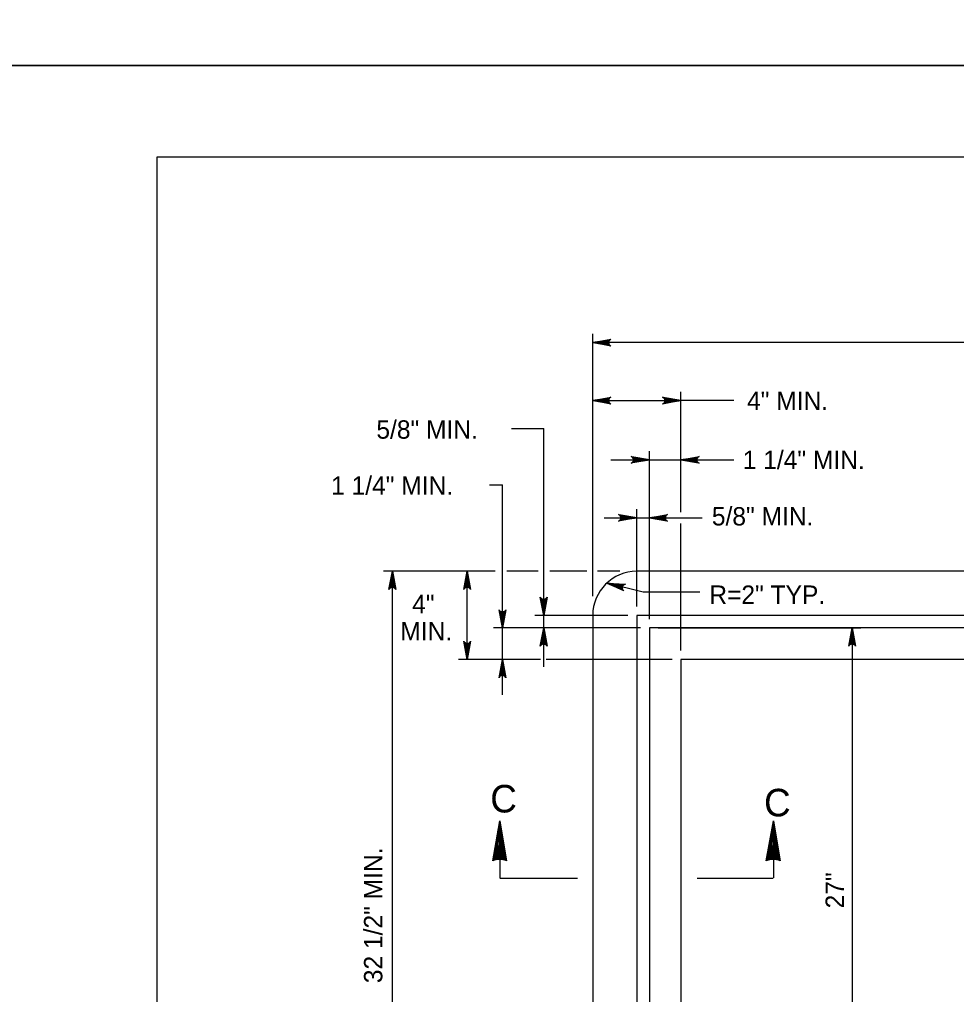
# Model space of a CAD drawing. Extents: x 2087776 to 2104538, y 970919 to 982612.
# Drawn here: x 2096108 to 2096610, y 976268 to 976790 of the extents above; entities that cross this region are included whole.
import ezdxf

# ---------------------------------------------------------------- set-up
doc = ezdxf.new("R2010")
doc.units = 0
doc.layers.add('1', color=7, linetype='Continuous')
doc.layers.add('PLT-BNDY', color=7, linetype='Continuous')

msp = doc.modelspace()

# ---------------------------------------------------------------- linework, layer by layer
at = {"layer": '1'}
for p, q in [((2096414.81, 976481.38), (2096414.81, 976622.01)), ((2096741.69, 976617.29), (2096414.81, 976617.29)), ((2096462.05, 976530.67), (2096462.05, 976590.95)), ((2096414.81, 976586.22), (2096462.05, 976586.22)), ((2096490.4, 976586.22), (2096462.05, 976586.22)), ((2096445.18, 976469.12), (2096445.18, 976559.18)), ((2096462.05, 976526.42), (2096462.05, 976559.18)), ((2096424.44, 976554.45), (2096490.4, 976554.45)), ((2096438.43, 976475.88), (2096438.43, 976528.11)), ((2096445.18, 976469.12), (2096445.18, 976528.11)), ((2096420.99, 976523.39), (2096473.52, 976523.39)), ((2096462.05, 976452.25), (2096462.05, 976520.3)), ((2096462.05, 976452.25), (2096462.05, 976515.36)), ((2096362.61, 976494.77), (2096302.73, 976494.77)), ((2096307.45, 976130.34), (2096307.45, 976494.77)), ((2096347.55, 976447.53), (2096347.55, 976494.77)), ((2096385.53, 976494.77), (2096368.86, 976494.77)), ((2096411.58, 976494.77), (2096391.78, 976494.77)), ((2096429.3, 976494.77), (2096417.31, 976494.77)), ((2096433.71, 976471.15), (2096383.84, 976471.15)), ((2096440.45, 976464.4), (2096361.72, 976464.4)), ((2096440.45, 976464.4), (2096383.84, 976464.4)), ((2096449.9, 976464.4), (2096558.58, 976464.4)), ((2096553.85, 976464.4), (2096553.85, 976160.71)), ((2096386.75, 976447.53), (2096342.82, 976447.53)), ((2096384.12, 976447.53), (2096361.72, 976447.53)), ((2096457.33, 976447.53), (2096389.92, 976447.53)), ((2096457.33, 976447.53), (2096391.61, 976447.53)), ((2096365, 976340.37), (2096365, 976330.5)), ((2096511.64, 976340.37), (2096511.64, 976330.5)), ((2096364.96, 976330.42), (2096406.6, 976330.42)), ((2096470.79, 976330.42), (2096511.6, 976330.42))]:
    msp.add_line(p, q, dxfattribs=at)
for points in [[(2098759.93, 974866.19), (2098759.93, 976716.58), (2096181.19, 976716.58), (2096181.19, 974866.19), (2098759.93, 974866.19), (2098759.93, 974952.67), (2098103.76, 974952.67), (2098103.76, 975164.86), (2098759.93, 975164.86), (2098759.93, 975259.89), (2098103.76, 975259.89), (2098103.76, 974866.19), (2098362.29, 974866.19), (2098362.29, 974952.67), (2098362.29, 974866.19), (2098614.92, 974866.19), (2098614.92, 974952.67), (2098614.92, 974912.26), (2098759.93, 974912.26)], [(2096414.81, 976617.29), (2096424.59, 976619.12), (2096424.22, 976618.86), (2096423.84, 976618.6), (2096423.65, 976618.27), (2096423.45, 976617.94), (2096423.4, 976617.61), (2096423.34, 976617.29), (2096423.4, 976616.96), (2096423.45, 976616.63), (2096423.65, 976616.3), (2096423.84, 976615.97), (2096424.22, 976615.71), (2096424.59, 976615.45), (2096414.81, 976617.29), (2096424.22, 976615.71), (2096423.84, 976615.97), (2096414.81, 976617.29), (2096423.65, 976616.3), (2096423.45, 976616.63), (2096414.81, 976617.29), (2096423.4, 976616.96), (2096423.34, 976617.29), (2096414.81, 976617.29), (2096423.4, 976617.61), (2096423.45, 976617.94), (2096414.81, 976617.29), (2096423.65, 976618.27), (2096423.84, 976618.6), (2096414.81, 976617.29), (2096424.22, 976618.86)], [(2096414.81, 976586.22), (2096424.59, 976588.06), (2096424.22, 976587.8), (2096423.84, 976587.54), (2096423.65, 976587.21), (2096423.45, 976586.88), (2096423.4, 976586.55), (2096423.34, 976586.22), (2096423.4, 976585.9), (2096423.45, 976585.57), (2096423.65, 976585.24), (2096423.84, 976584.91), (2096424.22, 976584.65), (2096424.59, 976584.39), (2096414.81, 976586.22), (2096424.22, 976584.65), (2096423.84, 976584.91), (2096414.81, 976586.22), (2096423.65, 976585.24), (2096423.45, 976585.57), (2096414.81, 976586.22), (2096423.4, 976585.9), (2096423.34, 976586.22), (2096414.81, 976586.22), (2096423.4, 976586.55), (2096423.45, 976586.88), (2096414.81, 976586.22), (2096423.65, 976587.21), (2096423.84, 976587.54), (2096414.81, 976586.22), (2096424.22, 976587.8)], [(2096462.05, 976586.22), (2096452.27, 976584.39), (2096452.64, 976584.65), (2096453.02, 976584.91), (2096453.22, 976585.24), (2096453.41, 976585.57), (2096453.47, 976585.9), (2096453.52, 976586.22), (2096453.47, 976586.55), (2096453.41, 976586.88), (2096453.22, 976587.21), (2096453.02, 976587.54), (2096452.64, 976587.8), (2096452.27, 976588.06), (2096462.05, 976586.22), (2096452.64, 976587.8), (2096453.02, 976587.54), (2096462.05, 976586.22), (2096453.22, 976587.21), (2096453.41, 976586.88), (2096462.05, 976586.22), (2096453.47, 976586.55), (2096453.52, 976586.22), (2096462.05, 976586.22), (2096453.47, 976585.9), (2096453.41, 976585.57), (2096462.05, 976586.22), (2096453.22, 976585.24), (2096453.02, 976584.91), (2096462.05, 976586.22), (2096452.64, 976584.65)], [(2096371.33, 976571.27), (2096388.56, 976571.27)], [(2096388.56, 976443.6), (2096388.56, 976571.27)], [(2096445.18, 976554.45), (2096435.39, 976552.62), (2096435.77, 976552.88), (2096436.14, 976553.14), (2096436.34, 976553.47), (2096436.53, 976553.8), (2096436.59, 976554.12), (2096436.65, 976554.45), (2096436.59, 976554.78), (2096436.53, 976555.11), (2096436.34, 976555.44), (2096436.14, 976555.76), (2096435.77, 976556.03), (2096435.39, 976556.29), (2096445.18, 976554.45), (2096435.77, 976556.03), (2096436.14, 976555.76), (2096445.18, 976554.45), (2096436.34, 976555.44), (2096436.53, 976555.11), (2096445.18, 976554.45), (2096436.59, 976554.78), (2096436.65, 976554.45), (2096445.18, 976554.45), (2096436.59, 976554.12), (2096436.53, 976553.8), (2096445.18, 976554.45), (2096436.34, 976553.47), (2096436.14, 976553.14), (2096445.18, 976554.45), (2096435.77, 976552.88)], [(2096462.05, 976554.45), (2096471.84, 976556.29), (2096471.46, 976556.03), (2096471.08, 976555.76), (2096470.89, 976555.44), (2096470.7, 976555.11), (2096470.64, 976554.78), (2096470.58, 976554.45), (2096470.64, 976554.12), (2096470.7, 976553.8), (2096470.89, 976553.47), (2096471.08, 976553.14), (2096471.46, 976552.88), (2096471.84, 976552.62), (2096462.05, 976554.45), (2096471.46, 976552.88), (2096471.08, 976553.14), (2096462.05, 976554.45), (2096470.89, 976553.47), (2096470.7, 976553.8), (2096462.05, 976554.45), (2096470.64, 976554.12), (2096470.58, 976554.45), (2096462.05, 976554.45), (2096470.64, 976554.78), (2096470.7, 976555.11), (2096462.05, 976554.45), (2096470.89, 976555.44), (2096471.08, 976555.76), (2096462.05, 976554.45), (2096471.46, 976556.03)], [(2096359.46, 976541.15), (2096366.44, 976541.15)], [(2096366.44, 976428.62), (2096366.44, 976541.15)], [(2096438.43, 976523.39), (2096428.65, 976521.55), (2096429.02, 976521.82), (2096429.4, 976522.08), (2096429.59, 976522.4), (2096429.79, 976522.73), (2096429.84, 976523.06), (2096429.9, 976523.39), (2096429.84, 976523.72), (2096429.79, 976524.05), (2096429.59, 976524.37), (2096429.4, 976524.7), (2096429.02, 976524.96), (2096428.65, 976525.22), (2096438.43, 976523.39), (2096429.02, 976524.96), (2096429.4, 976524.7), (2096438.43, 976523.39), (2096429.59, 976524.37), (2096429.79, 976524.05), (2096438.43, 976523.39), (2096429.84, 976523.72), (2096429.9, 976523.39), (2096438.43, 976523.39), (2096429.84, 976523.06), (2096429.79, 976522.73), (2096438.43, 976523.39), (2096429.59, 976522.4), (2096429.4, 976522.08), (2096438.43, 976523.39), (2096429.02, 976521.82)], [(2096445.18, 976523.39), (2096454.96, 976525.22), (2096454.58, 976524.96), (2096454.21, 976524.7), (2096454.01, 976524.37), (2096453.82, 976524.05), (2096453.76, 976523.72), (2096453.71, 976523.39), (2096453.76, 976523.06), (2096453.82, 976522.73), (2096454.01, 976522.4), (2096454.21, 976522.08), (2096454.58, 976521.82), (2096454.96, 976521.55), (2096445.18, 976523.39), (2096454.58, 976521.82), (2096454.21, 976522.08), (2096445.18, 976523.39), (2096454.01, 976522.4), (2096453.82, 976522.73), (2096445.18, 976523.39), (2096453.76, 976523.06), (2096453.71, 976523.39), (2096445.18, 976523.39), (2096453.76, 976523.72), (2096453.82, 976524.05), (2096445.18, 976523.39), (2096454.01, 976524.37), (2096454.21, 976524.7), (2096445.18, 976523.39), (2096454.58, 976524.96)], [(2096307.45, 976494.77), (2096309.29, 976484.99), (2096309.03, 976485.37), (2096308.77, 976485.74), (2096308.44, 976485.94), (2096308.11, 976486.13), (2096307.78, 976486.19), (2096307.45, 976486.24), (2096307.12, 976486.19), (2096306.8, 976486.13), (2096306.47, 976485.94), (2096306.14, 976485.74), (2096305.88, 976485.37), (2096305.62, 976484.99), (2096307.45, 976494.77), (2096305.88, 976485.37), (2096306.14, 976485.74), (2096307.45, 976494.77), (2096306.47, 976485.94), (2096306.8, 976486.13), (2096307.45, 976494.77), (2096307.12, 976486.19), (2096307.45, 976486.24), (2096307.45, 976494.77), (2096307.78, 976486.19), (2096308.11, 976486.13), (2096307.45, 976494.77), (2096308.44, 976485.94), (2096308.77, 976485.74), (2096307.45, 976494.77), (2096309.03, 976485.37)], [(2096347.55, 976494.77), (2096349.38, 976484.99), (2096349.12, 976485.37), (2096348.86, 976485.74), (2096348.53, 976485.94), (2096348.2, 976486.13), (2096347.88, 976486.19), (2096347.55, 976486.24), (2096347.22, 976486.19), (2096346.89, 976486.13), (2096346.56, 976485.94), (2096346.24, 976485.74), (2096345.97, 976485.37), (2096345.71, 976484.99), (2096347.55, 976494.77), (2096345.97, 976485.37), (2096346.24, 976485.74), (2096347.55, 976494.77), (2096346.56, 976485.94), (2096346.89, 976486.13), (2096347.55, 976494.77), (2096347.22, 976486.19), (2096347.55, 976486.24), (2096347.55, 976494.77), (2096347.88, 976486.19), (2096348.2, 976486.13), (2096347.55, 976494.77), (2096348.53, 976485.94), (2096348.86, 976485.74), (2096347.55, 976494.77), (2096349.12, 976485.37)], [(2096715.13, 976494.77), (2096438.43, 976494.77)], [(2096472.3, 976483.53), (2096445.29, 976483.53), (2096441.92, 976483.53), (2096422.38, 976488.48)], [(2096422.38, 976488.48), (2096432.32, 976487.86), (2096431.89, 976487.7), (2096431.46, 976487.54), (2096431.19, 976487.27), (2096430.92, 976487), (2096430.79, 976486.69), (2096430.65, 976486.39), (2096430.63, 976486.06), (2096430.6, 976485.72), (2096430.71, 976485.36), (2096430.82, 976484.99), (2096431.12, 976484.65), (2096431.42, 976484.3), (2096422.38, 976488.48), (2096431.12, 976484.65), (2096430.82, 976484.99), (2096422.38, 976488.48), (2096430.71, 976485.36), (2096430.6, 976485.72), (2096422.38, 976488.48), (2096430.63, 976486.06), (2096430.65, 976486.39), (2096422.38, 976488.48), (2096430.79, 976486.69), (2096430.92, 976487), (2096422.38, 976488.48), (2096431.19, 976487.27), (2096431.46, 976487.54), (2096422.38, 976488.48), (2096431.89, 976487.7)], [(2096388.56, 976471.15), (2096386.73, 976480.94), (2096386.99, 976480.56), (2096387.25, 976480.18), (2096387.58, 976479.99), (2096387.91, 976479.79), (2096388.23, 976479.74), (2096388.56, 976479.68), (2096388.89, 976479.74), (2096389.22, 976479.79), (2096389.55, 976479.99), (2096389.87, 976480.18), (2096390.14, 976480.56), (2096390.4, 976480.94), (2096388.56, 976471.15), (2096390.14, 976480.56), (2096389.87, 976480.18), (2096388.56, 976471.15), (2096389.55, 976479.99), (2096389.22, 976479.79), (2096388.56, 976471.15), (2096388.89, 976479.74), (2096388.56, 976479.68), (2096388.56, 976471.15), (2096388.23, 976479.74), (2096387.91, 976479.79), (2096388.56, 976471.15), (2096387.58, 976479.99), (2096387.25, 976480.18), (2096388.56, 976471.15), (2096386.99, 976480.56)], [(2096366.44, 976464.4), (2096364.61, 976474.19), (2096364.87, 976473.81), (2096365.13, 976473.43), (2096365.46, 976473.24), (2096365.79, 976473.04), (2096366.11, 976472.99), (2096366.44, 976472.93), (2096366.77, 976472.99), (2096367.1, 976473.04), (2096367.43, 976473.24), (2096367.75, 976473.43), (2096368.02, 976473.81), (2096368.28, 976474.19), (2096366.44, 976464.4), (2096368.02, 976473.81), (2096367.75, 976473.43), (2096366.44, 976464.4), (2096367.43, 976473.24), (2096367.1, 976473.04), (2096366.44, 976464.4), (2096366.77, 976472.99), (2096366.44, 976472.93), (2096366.44, 976464.4), (2096366.11, 976472.99), (2096365.79, 976473.04), (2096366.44, 976464.4), (2096365.46, 976473.24), (2096365.13, 976473.43), (2096366.44, 976464.4), (2096364.87, 976473.81)], [(2096414.81, 976471.15), (2096414.81, 976153.95)], [(2096715.13, 976471.15), (2096438.43, 976471.15), (2096438.43, 976153.95), (2096715.13, 976153.95)], [(2096388.56, 976464.4), (2096390.4, 976454.61), (2096390.14, 976454.99), (2096389.87, 976455.37), (2096389.55, 976455.56), (2096389.22, 976455.76), (2096388.89, 976455.81), (2096388.56, 976455.87), (2096388.23, 976455.81), (2096387.91, 976455.76), (2096387.58, 976455.56), (2096387.25, 976455.37), (2096386.99, 976454.99), (2096386.73, 976454.61), (2096388.56, 976464.4), (2096386.99, 976454.99), (2096387.25, 976455.37), (2096388.56, 976464.4), (2096387.58, 976455.56), (2096387.91, 976455.76), (2096388.56, 976464.4), (2096388.23, 976455.81), (2096388.56, 976455.87), (2096388.56, 976464.4), (2096388.89, 976455.81), (2096389.22, 976455.76), (2096388.56, 976464.4), (2096389.55, 976455.56), (2096389.87, 976455.37), (2096388.56, 976464.4), (2096390.14, 976454.99)], [(2096985.08, 976464.4), (2096445.18, 976464.4), (2096445.18, 976160.71), (2096985.08, 976160.71), (2096985.08, 976464.4)], [(2096553.85, 976464.4), (2096555.69, 976454.61), (2096555.42, 976454.99), (2096555.16, 976455.37), (2096554.83, 976455.56), (2096554.51, 976455.76), (2096554.18, 976455.81), (2096553.85, 976455.87), (2096553.52, 976455.81), (2096553.19, 976455.76), (2096552.87, 976455.56), (2096552.54, 976455.37), (2096552.28, 976454.99), (2096552.02, 976454.61), (2096553.85, 976464.4), (2096552.28, 976454.99), (2096552.54, 976455.37), (2096553.85, 976464.4), (2096552.87, 976455.56), (2096553.19, 976455.76), (2096553.85, 976464.4), (2096553.52, 976455.81), (2096553.85, 976455.87), (2096553.85, 976464.4), (2096554.18, 976455.81), (2096554.51, 976455.76), (2096553.85, 976464.4), (2096554.83, 976455.56), (2096555.16, 976455.37), (2096553.85, 976464.4), (2096555.42, 976454.99)], [(2096347.55, 976447.53), (2096345.71, 976457.32), (2096345.97, 976456.94), (2096346.24, 976456.56), (2096346.56, 976456.37), (2096346.89, 976456.17), (2096347.22, 976456.12), (2096347.55, 976456.06), (2096347.88, 976456.12), (2096348.2, 976456.17), (2096348.53, 976456.37), (2096348.86, 976456.56), (2096349.12, 976456.94), (2096349.38, 976457.32), (2096347.55, 976447.53), (2096349.12, 976456.94), (2096348.86, 976456.56), (2096347.55, 976447.53), (2096348.53, 976456.37), (2096348.2, 976456.17), (2096347.55, 976447.53), (2096347.88, 976456.12), (2096347.55, 976456.06), (2096347.55, 976447.53), (2096347.22, 976456.12), (2096346.89, 976456.17), (2096347.55, 976447.53), (2096346.56, 976456.37), (2096346.24, 976456.56), (2096347.55, 976447.53), (2096345.97, 976456.94)], [(2096366.44, 976447.53), (2096368.28, 976437.74), (2096368.02, 976438.12), (2096367.75, 976438.5), (2096367.43, 976438.69), (2096367.1, 976438.89), (2096366.77, 976438.94), (2096366.44, 976439), (2096366.11, 976438.94), (2096365.79, 976438.89), (2096365.46, 976438.69), (2096365.13, 976438.5), (2096364.87, 976438.12), (2096364.61, 976437.74), (2096366.44, 976447.53), (2096364.87, 976438.12), (2096365.13, 976438.5), (2096366.44, 976447.53), (2096365.46, 976438.69), (2096365.79, 976438.89), (2096366.44, 976447.53), (2096366.11, 976438.94), (2096366.44, 976439), (2096366.44, 976447.53), (2096366.77, 976438.94), (2096367.1, 976438.89), (2096366.44, 976447.53), (2096367.43, 976438.69), (2096367.75, 976438.5), (2096366.44, 976447.53), (2096368.02, 976438.12)], [(2096968.21, 976447.53), (2096462.05, 976447.53), (2096462.05, 976177.58), (2096968.21, 976177.58), (2096968.21, 976447.53)], [(2096361.21, 976339.64), (2096365, 976361.14), (2096368.7, 976339.64), (2096368.22, 976339.88), (2096368.27, 976342.15), (2096367.79, 976344.94), (2096367.73, 976340.03), (2096367.24, 976340.13), (2096367.21, 976348.28), (2096366.72, 976351.17), (2096366.73, 976340.26), (2096366.2, 976340.37), (2096366.21, 976354.11), (2096365.65, 976357.39), (2096365.66, 976340.43), (2096365.18, 976340.4), (2096365.17, 976360.15), (2096364.99, 976361.11), (2096364.52, 976358.35), (2096364.64, 976340.47), (2096364.15, 976340.39), (2096364.03, 976355.6), (2096363.55, 976352.89), (2096363.55, 976340.3), (2096363.08, 976340.3), (2096363.01, 976349.82), (2096362.46, 976346.72), (2096362.51, 976340.13), (2096361.97, 976339.99), (2096362, 976344.15), (2096361.45, 976341), (2096361.57, 976339.79)], [(2096507.85, 976339.64), (2096511.64, 976361.14), (2096515.34, 976339.64), (2096514.86, 976339.88), (2096514.91, 976342.15), (2096514.43, 976344.94), (2096514.37, 976340.03), (2096513.88, 976340.13), (2096513.85, 976348.28), (2096513.36, 976351.17), (2096513.37, 976340.26), (2096512.84, 976340.37), (2096512.86, 976354.11), (2096512.29, 976357.39), (2096512.3, 976340.43), (2096511.83, 976340.4), (2096511.81, 976360.15), (2096511.63, 976361.11), (2096511.16, 976358.35), (2096511.28, 976340.47), (2096510.79, 976340.39), (2096510.67, 976355.6), (2096510.19, 976352.89), (2096510.19, 976340.3), (2096509.73, 976340.3), (2096509.65, 976349.82), (2096509.1, 976346.72), (2096509.15, 976340.13), (2096508.61, 976339.99), (2096508.64, 976344.15), (2096508.09, 976341), (2096508.21, 976339.79)]]:
    msp.add_lwpolyline(points, dxfattribs=at)
for centre, radius, start, end in [((2096438.43, 976471.15), 23.62, 90, 180), ((2096364.96, 976330.42), 9.95, 67.8762, 112.1238), ((2096511.6, 976330.42), 9.95, 67.8762, 112.1238)]:
    msp.add_arc(centre, radius, start, end, dxfattribs=at)
at = {"layer": 'PLT-BNDY'}
for points in [[(2096053.23, 978714.61), (2098812.42, 978714.61), (2098812.42, 976765.79), (2096053.23, 976765.79)], [(2096053.23, 976765.79), (2098812.42, 976765.79), (2098812.42, 974816.97), (2096053.23, 974816.97)]]:
    msp.add_lwpolyline(points, close=True, dxfattribs=at)

# ---------------------------------------------------------------- texts
at = {"layer": '1'}
for s, height, p in [('4" MIN.', 9.843, (2096497.51, 976581.22)), ('5/8" MIN.', 9.843, (2096298.89, 976565.81)), ('1 1/4" MIN.', 9.8425, (2096495.21, 976549.55)), ('1 1/4" MIN.', 9.8425, (2096274.61, 976535.77)), ('5/8" MIN.', 9.843, (2096478.67, 976519.31)), ('R=2" TYP.', 9.843, (2096477.3, 976477.33)), ('4"', 9.843, (2096318.07, 976472.32)), ('MIN.', 9.843, (2096311.72, 976457.76)), ('C', 14.76, (2096359.93, 976365.56)), ('C', 14.76, (2096506.63, 976363.46))]:
    msp.add_text(s, height=height, dxfattribs=at).set_placement(p)
for s, height, p in [('32 1/2" MIN.', 9.8425, (2096302.08, 976274.1)), ('27"', 9.843, (2096549.43, 976314.17))]:
    msp.add_text(s, height=height, rotation=90, dxfattribs=at).set_placement(p)

doc.saveas('drawing.dxf')
